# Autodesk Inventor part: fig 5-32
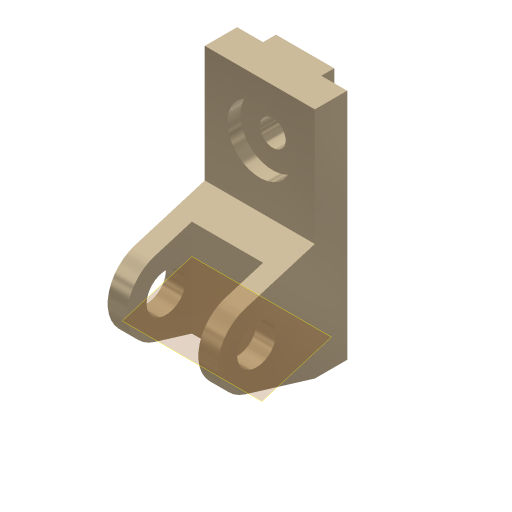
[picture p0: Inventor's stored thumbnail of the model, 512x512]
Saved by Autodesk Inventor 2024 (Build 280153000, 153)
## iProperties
Shininess: 65.0
Angle Display Precision: 2
Document Length Units: 11269
Document Angle Units: 11279
Document Time Units: 11290
Document Mass Units: 11283
Document Length Units Precision: 3
Document Angle Units Precision: 2
Created: 2001-11
Part Number: fig 5-32
Document SubType Name: Modeling
Designer: Renu Muthoo
Density: 1 g/cm^3
Material: Generic
Appearance: Metal-Titanium (Polished)
Density: 0.0
Volumn: 0.0
Area: 0.0
PropertySet Name: Model Information
Control State: 0
Master: False
Checked Out: False
Author: Renu Muthoo
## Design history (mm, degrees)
sketch "Sketch2"
  geometry: L1 (33.257, 104.664)-(33.257, -75.336); L2 (33.257, -75.336)-(8.257, -75.336); L3 (8.257, -75.336)-(-45.451, -59.045); L4 (-45.451, -1.628)-(8.257, 14.664); L5 (8.257, 14.664)-(8.257, 104.664); L6 (8.257, 104.664)-(33.257, 104.664); C1 r 15 at (-36.743, -30.336); A1 r 30 centre (-36.743, -30.336) between (-45.451, -1.628) and (-45.451, -59.045)
  constraints: 12 end point, 2 centre point, 2 equal length, 2 parallel, 2 point on circle, 2 tangent, 1 coincident, 1 perpendicular, 1 vertical
  dimensions: "d0" = 180 distance of L1.start L1.end; "d1" = 30 radius of A1; "d2" = 25 distance of L5.end L1.start; "d3" = 45 distance from line of L2 A1.centre; "d4" = 70 distance from line of L1 A1.centre; "d5" = 30 diameter of C1
extrude "Extrusion1" new body sketch "Sketch2" distance "d6" = 85; taper "d7" = 0 deg
workplane "Work Plane1"
sketch "Sketch3"
  geometry: L1 (15, 62.364)-(70, 62.364); L2 (70, 62.364)-(70, -52.386); L3 (70, -52.386)-(15, -52.386); L4 (15, -52.386)-(15, 62.364); L5 (0, -45)-(0, -28.708) reference
  constraints: 8 end point, 2 parallel, 1 horizontal, 1 perpendicular
  dimensions: "d8" = 55 distance of L1.start L1.end; "d9" = 15 distance between parallel lines of L5 L4
extrude "Extrusion2" cut sketch "Sketch3" distance "d10" = 50; taper "d11" = 0 deg
sketch "Sketch4"
  geometry: L1 (0, 25)-(85, 25) reference; L2 (0, 0)-(0, 25) reference; L3 (20, 25)-(65, 25); L4 (65, 25)-(65, 35); L5 (65, 35)-(20, 35); L6 (20, 35)-(20, 25)
  constraints: 8 end point, 2 parallel, 1 horizontal, 1 perpendicular, 1 point on line
  dimensions: "d12" = 45 distance of L4.end L5.end; "d13" = 10 distance of L3.end L4.end; "d14" = 20 distance between parallel lines of L2 L6
extrude "Extrusion3" join sketch "Sketch4" stored distance "d15" = 50; taper "d16" = 0 deg
sketch "Sketch5"
  geometry: L1 (85, 0)-(85, 90) reference; L2 (0, 90)-(85, 90) reference; 1 further point
  dimensions: "d17" = 42 distance from line of L2 point (42.5, 48); "d18" = 42.5 distance from line of L1 point (42.5, 48)
hole "Hole1" sketch "Sketch5" diameter "d19" = 20; stored, may be unused: countersink angle "d23" = 82 deg, drill point angle "d25" = 118 deg; dims "d20" = 6, "d21" = 50, "d22" = 10, "d24" = 8
workplane "Work Plane6"
body "Solid1"
node "Sketch1"
